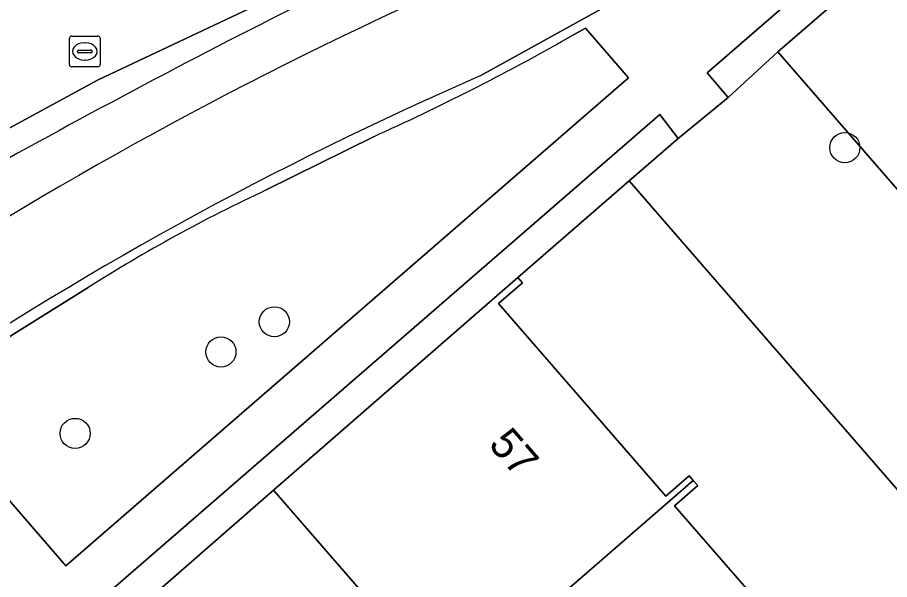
# Model space of a CAD drawing. Extents: x 155887 to 156869, y 383880 to 384678.
# Drawn here: x 156428.39 to 156456.68, y 384224.2 to 384242.44 of the extents above; entities that cross this region are included whole.
import ezdxf

# ---------------------------------------------------------------- set-up
doc = ezdxf.new("R2010")
doc.units = 0
for name, color, linetype in [('IMGEO_Boom', 7, 'Continuous'), ('IMGEO_Erf', 7, 'Continuous'), ('IMGEO_Fietspad_gesloten', 7, 'Continuous'), ('IMGEO_Greppel_droge_sloot', 7, 'Continuous'), ('IMGEO_Groenvoorziening', 7, 'Continuous'), ('IMGEO_Haag', 7, 'Continuous'), ('IMGEO_Kolk', 7, 'Continuous'), ('IMGEO_Pand', 7, 'Continuous'), ('IMGEO_Pand_nummerreeks', 7, 'Continuous'), ('IMGEO_Rijbaan_lokaal_open', 7, 'Continuous'), ('IMGEO_Voetpad_open', 7, 'Continuous')]:
    doc.layers.add(name, color=color, linetype=linetype)

msp = doc.modelspace()

# ---------------------------------------------------------------- linework, layer by layer
at = {"layer": 'IMGEO_Boom'}
for centre in [(156455.234, 384238.219), (156436.728, 384232.568), (156434.993, 384231.588), (156430.264, 384228.945)]:
    msp.add_circle(centre, 0.489, dxfattribs=at)
at = {"layer": 'IMGEO_Erf'}
for points in [[(156456.692, 384244.48), (156453.061, 384241.329), (156486.746, 384202.533)], [(156481.913, 384198.365), (156448.242, 384237.145), (156444.627, 384234), (156444.772, 384233.832), (156443.998, 384233.157), (156449.432, 384226.91), (156450.186, 384227.566), (156450.313, 384227.421), (156450.462, 384227.25), (156449.707, 384226.593), (156455.003, 384220.504), (156455.758, 384221.161), (156455.896, 384221.002), (156456.033, 384220.844), (156455.279, 384220.188), (156460.575, 384214.099)]]:
    msp.add_lwpolyline(points, dxfattribs=at)
msp.add_lwpolyline([(156431.662, 384222.698), (156434.212, 384219.753), (156434.994, 384218.854), (156440.046, 384223.245), (156436.696, 384227.099)], close=True, dxfattribs=at)
at = {"layer": 'IMGEO_Fietspad_gesloten'}
msp.add_lwpolyline([(156443.421, 384240.556), (156447.852, 384243.001), (156450.974, 384244.837), (156453.305, 384246.256), (156455.714, 384247.767), (156459.141, 384249.997), (156463.992, 384253.323)], dxfattribs=at)
for centre, radius, start, end in [((156495.005, 384125.191), 129.416, 114.13728, 123.94123), ((156490.594, 384132.335), 118.055, 113.55203, 124.16998)]:
    msp.add_arc(centre, radius, start, end, dxfattribs=at)
at = {"layer": 'IMGEO_Greppel_droge_sloot'}
msp.add_lwpolyline([(156422.17, 384235.612), (156431.011, 384240.417), (156441.343, 384245.302), (156439.756, 384248.536), (156429.512, 384243.914), (156420.131, 384239.079)], close=True, dxfattribs=at)
at = {"layer": 'IMGEO_Groenvoorziening'}
for points in [[(156474.433, 384259.907), (156482.386, 384266.814), (156486.351, 384270.258), (156487.652, 384271.39), (156486.985, 384272.131), (156475.218, 384261.843), (156461.558, 384250), (156450.764, 384240.642), (156451.452, 384239.846), (156453.061, 384241.329), (156456.692, 384244.48), (156463.052, 384250), (156464.634, 384251.373)], [(156422.17, 384235.612), (156420.131, 384239.079), (156429.512, 384243.914), (156439.756, 384248.536), (156441.343, 384245.302), (156431.011, 384240.417)], [(156444.627, 384234), (156448.242, 384237.145), (156449.822, 384238.517), (156449.232, 384239.291), (156431.01, 384223.489), (156431.662, 384222.698), (156436.696, 384227.099)]]:
    msp.add_lwpolyline(points, close=True, dxfattribs=at)
for points in [[(156429.967, 384224.649), (156448.218, 384240.488), (156446.819, 384242.097), (156446.238, 384241.767)], [(156439.938, 384238.572), (156436.466, 384236.845)], [(156430.687, 384233.676), (156425.137, 384230.216), (156429.967, 384224.649)]]:
    msp.add_lwpolyline(points, dxfattribs=at)
for centre, radius, start, end in [((156555.974, 384007.163), 263.775, 115.22336, 120.60653), ((156408.346, 384308.675), 76.893, 294.25881, 299.52423), ((156457.947, 384190.818), 50.793, 115.0189, 122.4588)]:
    msp.add_arc(centre, radius, start, end, dxfattribs=at)
at = {"layer": 'IMGEO_Haag'}
for points in [[(156474.433, 384259.907), (156482.386, 384266.814), (156486.351, 384270.258), (156487.652, 384271.39), (156486.985, 384272.131), (156475.218, 384261.843), (156461.558, 384250), (156450.764, 384240.642), (156451.452, 384239.846), (156453.061, 384241.329), (156456.692, 384244.48), (156463.052, 384250), (156464.634, 384251.373)], [(156444.627, 384234), (156448.242, 384237.145), (156449.822, 384238.517), (156449.232, 384239.291), (156431.01, 384223.489), (156431.662, 384222.698), (156436.696, 384227.099)]]:
    msp.add_lwpolyline(points, close=True, dxfattribs=at)
at = {"layer": 'IMGEO_Kolk'}
for p, q in [((156430.077, 384240.916), (156430.077, 384241.768)), ((156430.152, 384241.842), (156431.004, 384241.842)), ((156430.565, 384241.622), (156430.59, 384241.622)), ((156431.078, 384241.768), (156431.078, 384240.916)), ((156430.336, 384241.336), (156430.336, 384241.348)), ((156430.774, 384241.299), (156430.376, 384241.299)), ((156430.379, 384241.385), (156430.777, 384241.385)), ((156430.82, 384241.348), (156430.82, 384241.336)), ((156430.588, 384241.062), (156430.563, 384241.062)), ((156431.004, 384240.842), (156430.152, 384240.842))]:
    msp.add_line(p, q, dxfattribs=at)
for points in [[(156430.077, 384240.916), (156430.077, 384241.768)], [(156430.152, 384241.842), (156431.004, 384241.842)], [(156431.078, 384241.768), (156431.078, 384240.916)], [(156431.004, 384240.842), (156430.152, 384240.842)]]:
    msp.add_lwpolyline(points, dxfattribs=at)
for centre, radius, start, end in [((156430.154, 384241.766), 0.0765, 91.552, 178.448), ((156430.154, 384241.766), 0.0765, 91.552, 178.448), ((156431.002, 384241.766), 0.0765, 1.552, 88.448), ((156431.002, 384241.766), 0.0765, 1.552, 88.448), ((156430.376, 384241.345), 0.0403, 85.8775, 175.7526), ((156430.373, 384241.335), 0.0366, 178.938, 274.7102), ((156430.777, 384241.342), 0.043, 264.8664, 352.4533), ((156430.781, 384241.347), 0.0386, 1.7309, 96.639), ((156430.154, 384240.918), 0.0765, 181.552, 268.448), ((156430.154, 384240.918), 0.0765, 181.552, 268.448), ((156431.002, 384240.918), 0.0765, 271.552, 358.448), ((156431.002, 384240.918), 0.0765, 271.552, 358.448)]:
    msp.add_arc(centre, radius, start, end, dxfattribs=at)
for centre, major_axis, ratio, start_param, end_param in [((156430.564, 384241.342), (-0.387, 0.002), 0.722429, 4.712389, 7.853982), ((156430.589, 384241.342), (-0.39, 0.002), 0.717154, 1.570796, 4.712389)]:
    msp.add_ellipse(centre, major_axis=major_axis, ratio=ratio, start_param=start_param, end_param=end_param, dxfattribs=at)
at = {"layer": 'IMGEO_Pand'}
for points in [[(156436.696, 384227.099), (156440.046, 384223.245), (156434.994, 384218.854), (156437.347, 384216.151), (156450.313, 384227.421), (156450.186, 384227.566), (156449.432, 384226.91), (156443.998, 384233.157), (156444.772, 384233.832), (156444.627, 384234)], [(156455.896, 384221.002), (156455.758, 384221.161), (156455.003, 384220.504), (156449.707, 384226.593), (156450.462, 384227.25), (156450.313, 384227.421), (156437.347, 384216.151), (156439.717, 384213.427), (156442.463, 384215.814), (156445.62, 384212.183), (156447.922, 384214.184), (156447.974, 384214.124)]]:
    msp.add_lwpolyline(points, close=True, dxfattribs=at)
at = {"layer": 'IMGEO_Rijbaan_lokaal_open'}
msp.add_lwpolyline([(156453.061, 384241.329), (156451.452, 384239.846), (156449.822, 384238.517), (156448.242, 384237.145), (156481.913, 384198.365), (156486.746, 384202.533)], close=True, dxfattribs=at)
at = {"layer": 'IMGEO_Voetpad_open'}
for points in [[(156463.992, 384253.323), (156459.141, 384249.997), (156455.714, 384247.767), (156453.305, 384246.256), (156450.974, 384244.837), (156447.852, 384243.001), (156443.421, 384240.556)], [(156423.421, 384229.127), (156427.922, 384223.92), (156428.045, 384224.027), (156428.283, 384223.754), (156429.45, 384222.091), (156430.104, 384221.345), (156431.662, 384222.698), (156431.01, 384223.489), (156449.232, 384239.291), (156449.822, 384238.517), (156451.452, 384239.846), (156450.764, 384240.642), (156461.558, 384250)], [(156446.238, 384241.767), (156446.819, 384242.097), (156448.218, 384240.488), (156429.967, 384224.649)], [(156436.466, 384236.845), (156439.938, 384238.572)], [(156429.967, 384224.649), (156425.137, 384230.216), (156430.687, 384233.676)]]:
    msp.add_lwpolyline(points, dxfattribs=at)
for centre, radius, start, end in [((156555.974, 384007.163), 263.775, 115.22336, 120.60653), ((156495.005, 384125.191), 129.416, 114.13728, 123.94123), ((156408.346, 384308.675), 76.893, 294.25881, 299.52423), ((156490.594, 384132.335), 118.055, 113.55203, 124.16998), ((156457.947, 384190.818), 50.793, 115.0189, 122.4588)]:
    msp.add_arc(centre, radius, start, end, dxfattribs=at)

# ---------------------------------------------------------------- texts
at = {"layer": 'IMGEO_Pand_nummerreeks'}
msp.add_text('57', height=1, rotation=311.0175, dxfattribs=at).set_placement((156443.644, 384228.568))

doc.saveas('drawing.dxf')
